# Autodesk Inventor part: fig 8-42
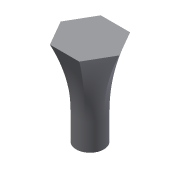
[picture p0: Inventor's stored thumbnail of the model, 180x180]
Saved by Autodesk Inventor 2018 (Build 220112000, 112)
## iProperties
Created: 2004-05
Part Number: fig 8-42
Document SubType Name: Modeling
Designer: CADCIM Technologies
Manufacturer: Standard
Standards Organization: Custom
Density: 1 g/cm^3
Material: Generic
Appearance: Default
Author: CADCIM Technologies
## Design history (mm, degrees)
sketch "Sketch1"
  geometry: C1 r 16.344 at (0, 0)
  constraints: 1 centre point
extrude "Extrusion1" new body sketch "Sketch1" distance "d0" = 30.75; taper "d1" = 0 deg
workplane "Work Plane1"
sketch "Sketch2"
  geometry: L1 (34.788, 0)-(17.394, -30.128); L2 (17.394, -30.128)-(-17.394, -30.128); L3 (-17.394, -30.128)-(-34.788, 0); L4 (-34.788, 0)-(-17.394, 30.128); L5 (-17.394, 30.128)-(17.394, 30.128); L6 (17.394, 30.128)-(34.788, 0); 2 further points
  constraints: 12 end point, 1 coincident, 12 other
loft "Loft2" sketch "Sketch2" dims "d8" = 90 deg, "d11" = 10, "d12" = 0, "d13" = 90 deg
  node "Edges2"
body "Solid1"
other parameters: "d2" = 75
